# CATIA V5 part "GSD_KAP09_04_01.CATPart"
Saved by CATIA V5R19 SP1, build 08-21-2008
Part number: GSD_REPETITION_03
Description: Beispielmodell: Rechteckmuster  Maik Hertha IT Consultants
Bounding box of the stored display mesh (mm): x 56.971 to 256.971, y 18.481 to 168.481, z 20 to 20
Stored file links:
  \GSD_LOFT\GSD_REPETITION_03.CATPart
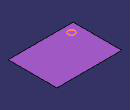
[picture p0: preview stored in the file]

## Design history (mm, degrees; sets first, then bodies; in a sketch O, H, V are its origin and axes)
AxisSystem1: origin (0, 0, 0), X (1, 0, 0), Y (0, 1, 0), Z (0, 0, 1)
Set1
  Plane1: type Equation, A 0, B 0, C 1, RefAxis AxisSystem1, Length 20
  Sketch1 on Plane1, origin (0, 0, 20), H (1, 0, 0), V (0, 1, 0)
    line L1 (56.9709, 168.4808) -> (256.9709, 168.4808)
    line L2 (256.9709, 168.4808) -> (256.9709, 18.4808)
    line L3 (256.9709, 18.4808) -> (56.9709, 18.4808)
    line L4 (56.9709, 18.4808) -> (56.9709, 168.4808)
    length L1 = 200
    length L2 = 150
    horizontal: L1 H, L3 H
    vertical: L2 V, L4 V
  Split1: ToCut Plane1, Cutting Sketch1
  Extremum1: Reference Split1, Direction2 (0, 1, 0), Direction3 (0, 0, 1), Direction (1, 0, 0)
  Point1: type OnPlane, Support Split1, Direction (1, 0, 0), H 30, V 25, RefPoint Extremum1
  Sketch2 on Plane1, origin (86.9709, 43.4808, 20), H (1, 0, 0), V (0, 1, 0)
    circle A1 centre (0, 0) radius 10
    point P1 (0, 0)
    curve C1
    construction line L1 (0, 21.4286) -> (0, -33.4496)
    point P2 (0, 21.4286)
    construction line L2 (-24.319, 0) -> (23.4536, 0)
    point P4 (-24.319, 0)
    radius A1 = 10
    coincidence: P2 V, P4 H, P1 L2, P1 L1
    vertical: L1 V
    horizontal: L2 H
Body1 (main body)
